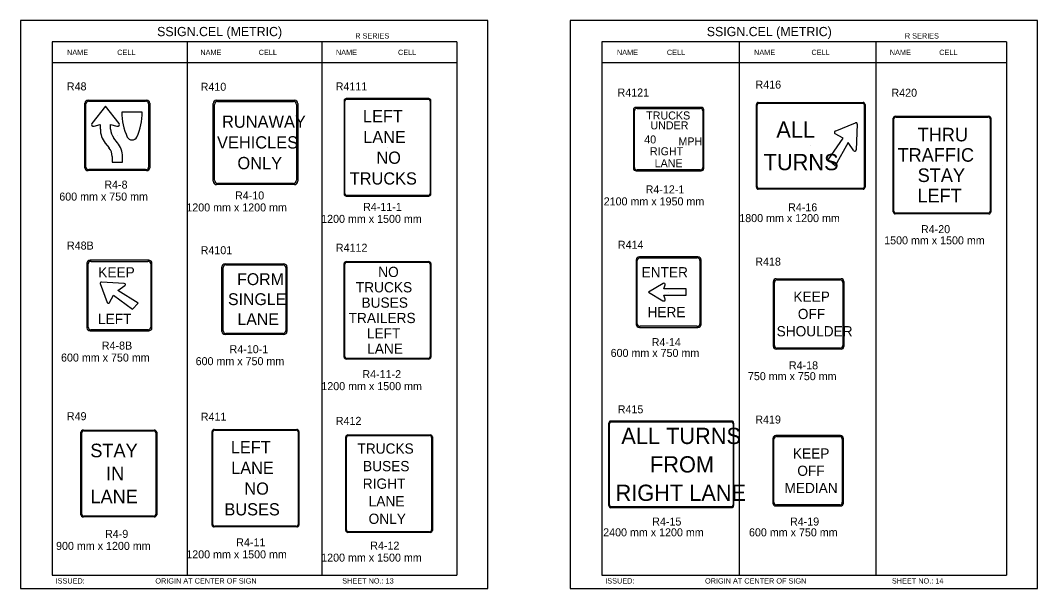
# Model space of a CAD drawing. Extents: x -12 to 6962, y -3756 to 679.
# Drawn here: x -11.9 to 369.4, y -235.4 to -22.3 of the extents above; entities that cross this region are included whole.
import ezdxf

# ---------------------------------------------------------------- set-up
doc = ezdxf.new("R2010")
doc.units = 0
for name, color, linetype in [('Level 1', 7, 'Continuous'), ('Level 2', 7, 'Continuous'), ('Level 3', 7, 'Continuous'), ('Level 63', 7, 'Continuous')]:
    doc.layers.add(name, color=color, linetype=linetype)

msp = doc.modelspace()

# ---------------------------------------------------------------- linework, layer by layer
at = {"layer": 'Level 1'}
for p, q in [((151.75, -30.35), (0, -30.35)), ((0, -30.35), (0, -230.35)), ((50.58, -30.35), (50.58, -230.35)), ((101.17, -30.35), (101.17, -230.35)), ((151.75, -30.35), (151.75, -230.35)), ((357.75, -30.35), (205.99, -30.35)), ((205.99, -30.35), (205.99, -230.35)), ((257.54, -30.35), (257.54, -230.35)), ((308.7, -30.35), (308.7, -230.35)), ((357.75, -30.35), (357.75, -230.35)), ((151.75, -38.27), (0, -38.27)), ((357.75, -38.27), (205.99, -38.27)), ((13.85, -52.65), (35.07, -52.65)), ((62.06, -52.68), (90.47, -52.68)), ((109.78, -87.26), (109.78, -52.58)), ((110.53, -51.91), (140.93, -51.91)), ((141.68, -52.58), (141.68, -87.26)), ((12.72, -77.3), (12.72, -53.63)), ((20.02, -54.53), (14.89, -60.96)), ((25.13, -60.96), (20.02, -54.53)), ((33.83, -56.72), (26.15, -56.72)), ((36.2, -53.63), (36.2, -77.3)), ((60.88, -82.26), (60.88, -53.85)), ((91.64, -53.85), (91.64, -82.26)), ((218.26, -77.51), (218.26, -56.2)), ((219.23, -55.32), (242.91, -55.32)), ((243.89, -56.2), (243.89, -77.51)), ((264.22, -84.56), (264.22, -54.16)), ((264.85, -53.41), (303.8, -53.41)), ((304.42, -54.16), (304.42, -84.56)), ((293.51, -63.87), (301.15, -60.71)), ((315.54, -93.92), (315.54, -59.24)), ((316.21, -58.56), (350.89, -58.56)), ((351.57, -59.24), (351.57, -93.92)), ((15.79, -61.99), (18.09, -61.38)), ((18.09, -61.38), (18.09, -63.12)), ((21.93, -63.12), (21.93, -61.38)), ((21.93, -61.38), (24.24, -61.99)), ((301.73, -61.24), (301.32, -70.92)), ((19.94, -68.31), (21.35, -70.07)), ((24.53, -68.19), (23.12, -66.44)), ((24.46, -65.46), (24.46, -65.46)), ((76.26, -68.06), (76.26, -68.06)), ((290.87, -74.61), (296.5, -66.44)), ((298.41, -68.17), (293.43, -76.9)), ((296.5, -66.44), (293.48, -64.86)), ((300.53, -71.24), (298.41, -68.17)), ((125.73, -69.92), (125.73, -69.92)), ((284.32, -69.36), (284.32, -69.36)), ((22.54, -73.38), (22.54, -75.46)), ((22.54, -75.46), (26.38, -75.46)), ((26.38, -75.46), (26.38, -73.38)), ((293.43, -76.9), (290.87, -74.61)), ((35.07, -78.28), (13.85, -78.28)), ((242.91, -78.39), (219.23, -78.39)), ((333.55, -76.58), (333.55, -76.58)), ((60.88, -82.26), (60.88, -82.26)), ((90.47, -83.44), (62.06, -83.44)), ((303.8, -85.31), (264.85, -85.31)), ((140.93, -87.94), (110.53, -87.94)), ((350.89, -94.59), (316.21, -94.59)), ((13.52, -137.34), (13.52, -113.66)), ((14.65, -112.69), (35.87, -112.69)), ((37, -113.66), (37, -137.34)), ((65.24, -114.04), (86.46, -114.04)), ((109.78, -148.37), (109.78, -113.69)), ((110.53, -113.01), (140.93, -113.01)), ((141.68, -113.69), (141.68, -148.37)), ((219.34, -136.05), (219.34, -112.38)), ((220.47, -111.4), (241.69, -111.4)), ((242.82, -112.38), (242.82, -136.05)), ((64.11, -138.69), (64.11, -115.02)), ((87.59, -115.02), (87.59, -138.69)), ((18.05, -121.02), (20.71, -128.12)), ((27.07, -121.02), (18.52, -120.51)), ((24.61, -123.66), (27.34, -121.73)), ((228.97, -120.95), (223.52, -124.19)), ((229.3, -123.04), (229.83, -121.52)), ((270.73, -144.24), (270.73, -120.57)), ((271.71, -119.59), (295.38, -119.59)), ((296.36, -120.57), (296.36, -144.24)), ((21.57, -128.15), (23.05, -125.38)), ((23.05, -125.38), (30.15, -130.66)), ((32.25, -128.36), (24.61, -123.66)), ((25.26, -125.5), (25.26, -125.5)), ((223.52, -124.19), (228.95, -127.45)), ((229.83, -126.88), (229.28, -125.36)), ((229.28, -125.36), (237.63, -125.36)), ((237.63, -123.04), (229.3, -123.04)), ((231.08, -124.21), (231.08, -124.21)), ((237.63, -125.36), (237.63, -123.04)), ((30.15, -130.66), (32.25, -128.36)), ((75.85, -126.85), (75.85, -126.85)), ((125.73, -131.03), (125.73, -131.03)), ((283.55, -132.41), (283.55, -132.41)), ((241.69, -137.03), (220.47, -137.03)), ((35.87, -138.32), (14.65, -138.32)), ((86.46, -139.67), (65.24, -139.67)), ((295.38, -145.22), (271.71, -145.22)), ((140.93, -149.04), (110.53, -149.04)), ((208.92, -203.99), (208.92, -173.59)), ((209.46, -172.84), (254.68, -172.84)), ((255.22, -173.59), (255.22, -203.99)), ((11.14, -207.42), (11.14, -177.02)), ((12.02, -176.26), (38.01, -176.26)), ((38.89, -177.02), (38.89, -207.42)), ((60.28, -211.32), (60.28, -176.65)), ((61.04, -175.97), (91.44, -175.97)), ((92.19, -176.65), (92.19, -211.32)), ((110.06, -213.58), (110.06, -178.47)), ((110.36, -213.36), (110.36, -178.69)), ((110.87, -177.74), (141.76, -177.74)), ((111.11, -178.01), (141.51, -178.01)), ((142.27, -178.69), (142.27, -213.36)), ((142.57, -178.47), (142.57, -213.58)), ((271.51, -178.37), (295.19, -178.37)), ((270.53, -203.03), (270.53, -179.35)), ((296.16, -179.35), (296.16, -203.03)), ((232.07, -188.79), (232.07, -188.79)), ((25.02, -192.22), (25.02, -192.22)), ((76.24, -193.99), (76.24, -193.99)), ((283.35, -191.19), (283.35, -191.19)), ((126.31, -196.03), (126.31, -196.03)), ((126.31, -196.03), (126.31, -196.03)), ((254.68, -204.74), (209.46, -204.74)), ((295.19, -204), (271.51, -204)), ((38.01, -208.17), (12.02, -208.17)), ((91.44, -212), (61.04, -212)), ((141.76, -214.31), (110.87, -214.31)), ((141.51, -214.04), (111.11, -214.04)), ((0, -230.35), (151.75, -230.35)), ((205.99, -230.35), (357.75, -230.35))]:
    msp.add_line(p, q, dxfattribs=at)
for centre, radius, start, end in [((62.06, -53.85), 1.17, 90, 180), ((90.47, -53.85), 1.17, 0, 90), ((316.21, -59.24), 0.677, 90, 180), ((350.89, -59.24), 0.677, 0, 90), ((62.06, -82.26), 1.17, 180, 270), ((90.47, -82.26), 1.17, 270, 0), ((316.21, -93.92), 0.677, 180, 270), ((350.89, -93.92), 0.677, 270, 0), ((271.71, -120.57), 0.977, 90, 180), ((271.71, -144.24), 0.977, 180, 270), ((295.38, -144.24), 0.977, 270, 0), ((271.51, -179.35), 0.977, 90, 180), ((295.19, -179.35), 0.977, 0, 90), ((271.51, -203.03), 0.977, 180, 270), ((295.19, -203.03), 0.977, 270, 0)]:
    msp.add_arc(centre, radius, start, end, dxfattribs=at)
for centre, major_axis, ratio, start_param, end_param in [((13.85, -53.63), (-1.13, 0), 0.866667, 4.712389, 6.283185), ((35.07, -53.63), (-1.13, 0), 0.866667, 3.141593, 4.712389), ((110.53, -52.58), (-0.752, 0), 0.9, 4.712389, 6.283185), ((140.93, -52.58), (-0.752, 0), 0.9, 3.141593, 4.712389), ((55.02, -56.8), (-28.87, 0), 0.866667, 6.279909, 6.663033), ((5.07, -56.82), (28.76, 0), 0.866667, 5.902613, 6.287187), ((219.23, -56.2), (-0.977, 0), 0.9, 4.712389, 6.283185), ((242.91, -56.2), (-0.977, 0), 0.9, 3.141593, 4.712389), ((264.85, -54.16), (0, -0.752), 0.83475, 3.141593, 4.712389), ((303.8, -54.16), (0, 0.752), 0.83475, 4.712389, 6.283185), ((15.57, -61.33), (-0.801, 0), 0.866667, 5.710118, 8.143254), ((24.47, -61.33), (0.801, 0), 0.866667, 4.423116, 6.856252), ((301.29, -61.22), (0, -0.534), 0.83475, 1.527577, 3.478447), ((28.72, -63.12), (10.62, 0), 0.866667, 3.14236, 3.740294), ((28.66, -63.13), (6.72, 0), 0.866667, 3.141339, 3.744924), ((293.64, -64.37), (0, -0.53), 0.83475, 3.451897, 5.881452), ((15.81, -73.38), (-10.57, 0), 0.866667, 3.141593, 3.744195), ((29.99, -65.47), (1.92, 0), 0.866667, 3.517117, 5.907661), ((15.85, -73.38), (6.69, 0), 0.866667, 6.282648, 6.891725), ((300.87, -70.9), (0, 0.529), 0.83475, 2.250511, 4.671837), ((13.85, -77.3), (1.13, 0), 0.866667, 3.141593, 4.712389), ((35.07, -77.3), (1.13, 0), 0.866667, 4.712389, 6.283185), ((219.23, -77.51), (0.977, 0), 0.9, 3.141593, 4.712389), ((242.91, -77.51), (0.977, 0), 0.9, 4.712389, 6.283185), ((110.53, -87.26), (0.752, 0), 0.9, 3.141593, 4.712389), ((140.93, -87.26), (0.752, 0), 0.9, 4.712389, 6.283185), ((264.85, -84.56), (0, -0.752), 0.83475, 4.712389, 6.283185), ((303.8, -84.56), (0, 0.752), 0.83475, 3.141593, 4.712389), ((14.65, -113.66), (-1.13, 0), 0.866667, 4.712389, 6.283185), ((35.87, -113.66), (-1.13, 0), 0.866667, 3.141593, 4.712389), ((65.24, -115.02), (-1.13, 0), 0.866667, 4.712389, 6.283185), ((86.46, -115.02), (-1.13, 0), 0.866667, 3.141593, 4.712389), ((110.53, -113.69), (-0.752, 0), 0.9, 4.712389, 6.283185), ((140.93, -113.69), (-0.752, 0), 0.9, 3.141593, 4.712389), ((220.47, -112.38), (-1.13, 0), 0.866667, 4.712389, 6.283185), ((241.69, -112.38), (-1.13, 0), 0.866667, 3.141593, 4.712389), ((18.49, -120.9), (-0.473, 0), 0.866667, 4.637334, 6.588204), ((27.06, -121.42), (0.469, 0), 0.866667, 5.375922, 7.805476), ((229.26, -121.38), (0.592, 0), 0.866667, 6.014589, 8.386103), ((21.14, -127.99), (0.469, 0), 0.866667, 3.443944, 5.86527), ((229.26, -127.02), (-0.598, 0), 0.866667, 1.019875, 3.40872), ((220.47, -136.05), (1.13, 0), 0.866667, 3.141593, 4.712389), ((241.69, -136.05), (1.13, 0), 0.866667, 4.712389, 6.283185), ((14.65, -137.34), (1.13, 0), 0.866667, 3.141593, 4.712389), ((35.87, -137.34), (1.13, 0), 0.866667, 4.712389, 6.283185), ((65.24, -138.69), (1.13, 0), 0.866667, 3.141593, 4.712389), ((86.46, -138.69), (1.13, 0), 0.866667, 4.712389, 6.283185), ((110.53, -148.37), (0.752, 0), 0.9, 3.141593, 4.712389), ((140.93, -148.37), (0.752, 0), 0.9, 4.712389, 6.283185), ((209.46, -173.59), (0, -0.752), 0.71875, 3.141593, 4.712389), ((254.68, -173.59), (0, 0.752), 0.71875, 4.712389, 6.283185), ((12.02, -177.02), (-0.877, 0), 0.857082, 4.712389, 6.283185), ((38.01, -177.02), (-0.877, 0), 0.857082, 3.141593, 4.712389), ((61.04, -176.65), (-0.752, 0), 0.9, 4.712389, 6.283185), ((91.44, -176.65), (-0.752, 0), 0.9, 3.141593, 4.712389), ((110.87, -178.47), (-0.813, 0), 0.9, 4.712389, 6.283185), ((111.11, -178.69), (-0.752, 0), 0.9, 4.712389, 6.283185), ((141.51, -178.69), (-0.752, 0), 0.9, 3.141593, 4.712389), ((141.76, -178.47), (-0.813, 0), 0.9, 3.141593, 4.712389), ((209.46, -203.99), (0, -0.752), 0.71875, 4.712389, 6.283185), ((254.68, -203.99), (0, 0.752), 0.71875, 3.141593, 4.712389), ((12.02, -207.42), (0.877, 0), 0.857082, 3.141593, 4.712389), ((38.01, -207.42), (0.877, 0), 0.857082, 4.712389, 6.283185), ((61.04, -211.32), (0.752, 0), 0.9, 3.141593, 4.712389), ((91.44, -211.32), (0.752, 0), 0.9, 4.712389, 6.283185), ((111.11, -213.36), (0.752, 0), 0.9, 3.141593, 4.712389), ((141.51, -213.36), (0.752, 0), 0.9, 4.712389, 6.283185), ((110.87, -213.58), (0.813, 0), 0.9, 3.141593, 4.712389), ((141.76, -213.58), (0.813, 0), 0.9, 4.712389, 6.283185)]:
    msp.add_ellipse(centre, major_axis=major_axis, ratio=ratio, start_param=start_param, end_param=end_param, dxfattribs=at)
at = {"layer": 'Level 3'}
for p, q in [((12.27, -77.61), (12.27, -53.31)), ((13.49, -52.26), (35.43, -52.26)), ((36.65, -53.31), (36.65, -77.61)), ((61.68, -52.21), (90.84, -52.21)), ((109.47, -52.37), (109.47, -87.48)), ((141.17, -51.64), (110.29, -51.64)), ((141.98, -87.48), (141.98, -52.37)), ((264.65, -53.1), (304, -53.1)), ((60.41, -82.64), (60.41, -53.48)), ((92.11, -53.48), (92.11, -82.64)), ((217.86, -55.92), (217.86, -77.79)), ((243.22, -54.97), (218.92, -54.97)), ((244.28, -77.79), (244.28, -55.92)), ((263.97, -84.8), (263.97, -53.92)), ((304.68, -53.92), (304.68, -84.8)), ((315.27, -94.13), (315.27, -59.02)), ((316, -58.29), (351.11, -58.29)), ((351.84, -59.02), (351.84, -94.13)), ((35.43, -78.67), (13.49, -78.67)), ((218.92, -78.74), (243.22, -78.74)), ((90.84, -83.91), (61.68, -83.91)), ((304, -85.61), (264.65, -85.61)), ((110.29, -88.21), (141.17, -88.21)), ((351.11, -94.86), (316, -94.86)), ((13.07, -113.35), (13.07, -137.65)), ((36.23, -112.29), (14.29, -112.29)), ((37.45, -137.65), (37.45, -113.35)), ((64.88, -113.65), (86.82, -113.65)), ((109.47, -148.58), (109.47, -113.47)), ((110.29, -112.74), (141.17, -112.74)), ((141.98, -113.47), (141.98, -148.58)), ((218.89, -112.06), (218.89, -136.36)), ((242.05, -111.01), (220.11, -111.01)), ((243.27, -136.36), (243.27, -112.06)), ((63.66, -139.01), (63.66, -114.7)), ((88.04, -114.7), (88.04, -139.01)), ((270.34, -144.56), (270.34, -120.26)), ((271.39, -119.2), (295.7, -119.2)), ((296.75, -120.26), (296.75, -144.56)), ((14.29, -138.71), (36.23, -138.71)), ((86.82, -140.06), (64.88, -140.06)), ((220.11, -137.42), (242.05, -137.42)), ((295.7, -145.61), (271.39, -145.61)), ((141.17, -149.32), (110.29, -149.32)), ((208.7, -204.23), (208.7, -173.35)), ((209.29, -172.53), (254.85, -172.53)), ((255.43, -173.35), (255.43, -204.23)), ((10.79, -207.66), (10.79, -176.78)), ((11.74, -175.96), (38.29, -175.96)), ((39.24, -176.78), (39.24, -207.66)), ((59.98, -211.54), (59.98, -176.43)), ((60.79, -175.7), (91.68, -175.7)), ((92.49, -176.43), (92.49, -211.54)), ((110.06, -213.58), (110.06, -178.47)), ((110.87, -177.74), (141.76, -177.74)), ((142.57, -178.47), (142.57, -213.58)), ((270.14, -179.04), (270.14, -203.34)), ((295.5, -177.98), (271.2, -177.98)), ((296.56, -203.34), (296.56, -179.04)), ((254.85, -205.04), (209.29, -205.04)), ((271.2, -204.4), (295.5, -204.4)), ((38.29, -208.47), (11.74, -208.47)), ((91.68, -212.27), (60.79, -212.27)), ((141.76, -214.31), (110.87, -214.31))]:
    msp.add_line(p, q, dxfattribs=at)
for centre, radius, start, end in [((61.68, -53.48), 1.27, 90, 180), ((90.84, -53.48), 1.27, 0, 90), ((316, -59.02), 0.731, 90, 180), ((351.11, -59.02), 0.731, 0, 90), ((61.68, -82.64), 1.27, 180, 270), ((90.84, -82.64), 1.27, 270, 0), ((316, -94.13), 0.731, 180, 270), ((351.11, -94.13), 0.731, 270, 0), ((271.39, -120.26), 1.06, 90, 180), ((295.38, -120.57), 0.977, 0, 90), ((295.7, -120.26), 1.06, 0, 90), ((271.39, -144.56), 1.06, 180, 270), ((295.7, -144.56), 1.06, 270, 0), ((271.2, -179.04), 1.06, 90, 180), ((295.5, -179.04), 1.06, 0, 90), ((271.2, -203.34), 1.06, 180, 270), ((295.5, -203.34), 1.06, 270, 0)]:
    msp.add_arc(centre, radius, start, end, dxfattribs=at)
for centre, major_axis, ratio, start_param, end_param in [((13.49, -53.31), (-1.22, 0), 0.866667, 4.712389, 6.283185), ((35.43, -53.31), (-1.22, 0), 0.866667, 3.141593, 4.712389), ((110.29, -52.37), (-0.813, 0), 0.9, 4.712389, 6.283185), ((141.17, -52.37), (-0.813, 0), 0.9, 3.141593, 4.712389), ((264.65, -53.92), (0, -0.813), 0.83475, 3.141593, 4.712389), ((304, -53.92), (0, 0.813), 0.83475, 4.712389, 6.283185), ((218.92, -55.92), (-1.06, 0), 0.9, 4.712389, 6.283185), ((243.22, -55.92), (-1.06, 0), 0.9, 3.141593, 4.712389), ((13.49, -77.61), (1.22, 0), 0.866667, 3.141593, 4.712389), ((35.43, -77.61), (1.22, 0), 0.866667, 4.712389, 6.283185), ((218.92, -77.79), (1.06, 0), 0.9, 3.141593, 4.712389), ((243.22, -77.79), (1.06, 0), 0.9, 4.712389, 6.283185), ((110.29, -87.48), (0.813, 0), 0.9, 3.141593, 4.712389), ((141.17, -87.48), (0.813, 0), 0.9, 4.712389, 6.283185), ((264.65, -84.8), (0, -0.813), 0.83475, 4.712389, 6.283185), ((304, -84.8), (0, 0.813), 0.83475, 3.141593, 4.712389), ((14.29, -113.35), (-1.22, 0), 0.866667, 4.712389, 6.283185), ((36.23, -113.35), (-1.22, 0), 0.866667, 3.141593, 4.712389), ((64.88, -114.7), (-1.22, 0), 0.866667, 4.712389, 6.283185), ((86.82, -114.7), (-1.22, 0), 0.866667, 3.141593, 4.712389), ((110.29, -113.47), (-0.813, 0), 0.9, 4.712389, 6.283185), ((141.17, -113.47), (-0.813, 0), 0.9, 3.141593, 4.712389), ((220.11, -112.06), (-1.22, 0), 0.866667, 4.712389, 6.283185), ((242.05, -112.06), (-1.22, 0), 0.866667, 3.141593, 4.712389), ((220.11, -136.36), (1.22, 0), 0.866667, 3.141593, 4.712389), ((242.05, -136.36), (1.22, 0), 0.866667, 4.712389, 6.283185), ((14.29, -137.65), (1.22, 0), 0.866667, 3.141593, 4.712389), ((36.23, -137.65), (1.22, 0), 0.866667, 4.712389, 6.283185), ((64.88, -139.01), (1.22, 0), 0.866667, 3.141593, 4.712389), ((86.82, -139.01), (1.22, 0), 0.866667, 4.712389, 6.283185), ((110.29, -148.58), (0.813, 0), 0.9, 3.141593, 4.712389), ((141.17, -148.58), (0.813, 0), 0.9, 4.712389, 6.283185), ((209.29, -173.35), (0, -0.813), 0.71875, 3.141593, 4.712389), ((254.85, -173.35), (0, 0.813), 0.71875, 4.712389, 6.283185), ((11.74, -176.78), (-0.948, 0), 0.857082, 4.712389, 6.283185), ((38.29, -176.78), (-0.948, 0), 0.857082, 3.141593, 4.712389), ((60.79, -176.43), (-0.813, 0), 0.9, 4.712389, 6.283185), ((91.68, -176.43), (-0.813, 0), 0.9, 3.141593, 4.712389), ((110.87, -178.47), (-0.813, 0), 0.9, 4.712389, 6.283185), ((141.76, -178.47), (-0.813, 0), 0.9, 3.141593, 4.712389), ((209.29, -204.23), (0, -0.813), 0.71875, 4.712389, 6.283185), ((254.85, -204.23), (0, 0.813), 0.71875, 3.141593, 4.712389), ((11.74, -207.66), (0.948, 0), 0.857082, 3.141593, 4.712389), ((38.29, -207.66), (0.948, 0), 0.857082, 4.712389, 6.283185), ((60.79, -211.54), (0.813, 0), 0.9, 3.141593, 4.712389), ((91.68, -211.54), (0.813, 0), 0.9, 4.712389, 6.283185), ((110.87, -213.58), (0.813, 0), 0.9, 3.141593, 4.712389), ((141.76, -213.58), (0.813, 0), 0.9, 4.712389, 6.283185)]:
    msp.add_ellipse(centre, major_axis=major_axis, ratio=ratio, start_param=start_param, end_param=end_param, dxfattribs=at)
at = {"layer": 'Level 63'}
for points in [[(-11.88, -235.4), (163.38, -235.4), (163.38, -22.31), (-11.88, -22.31)], [(194.12, -235.4), (369.38, -235.4), (369.38, -22.31), (194.12, -22.31)]]:
    msp.add_lwpolyline(points, close=True, dxfattribs=at)

# ---------------------------------------------------------------- texts
at = {"layer": 'Level 1'}
for s, height, p in [('LEFT', 4.572, (116.51, -60.55)), ('TRUCKS', 3, (222.67, -59.48)), ('RUNAWAY', 4.596, (63.71, -62.59)), ('UNDER', 3, (224.24, -63.18)), ('ALL', 6.096, (271.44, -66.31)), ('LANE', 4.572, (116.63, -68.32)), ('THRU', 5.08, (324.41, -67.69)), ('VEHICLES', 4.596, (61.83, -70.36)), ('40', 3, (221.94, -68.47)), ('MPH', 3, (234.75, -69.2)), ('NO', 4.572, (121.57, -76.09)), ('RIGHT', 3, (224.07, -72.9)), ('TURNS', 6.096, (266.7, -78.5)), ('TRAFFIC', 5.08, (316.87, -75.31)), ('ONLY', 4.596, (69.48, -78.12)), ('LANE', 3, (225.83, -77.39)), ('TRUCKS', 4.572, (111.59, -83.87)), ('STAY', 5.08, (324.41, -82.93)), ('LEFT', 5.08, (324.33, -90.55)), ('KEEP', 3.83, (17.33, -118.69)), ('FORM', 4.445, (69.38, -121.58)), ('NO', 3.84, (122.24, -118.55)), ('ENTER', 3.83, (220.95, -118.68)), ('TRUCKS', 3.84, (113.85, -124.31)), ('SINGLE', 4.445, (65.95, -129.08)), ('KEEP', 3.83, (277.85, -127.85)), ('BUSES', 3.84, (115.97, -130.07)), ('LEFT', 3.83, (17.24, -136.18)), ('LANE', 4.445, (69.48, -136.57)), ('TRAILERS', 3.84, (111.15, -135.83)), ('HERE', 3.83, (223.16, -133.63)), ('OFF', 3.83, (279.5, -134.32)), ('SHOULDER', 3.83, (271.56, -140.79)), ('LEFT', 3.84, (117.99, -141.59)), ('LANE', 3.84, (118.09, -147.35)), ('ALL TURNS', 6.096, (213.35, -181.17)), ('STAY', 5.08, (14.35, -186.12)), ('LEFT', 4.572, (67.02, -184.61)), ('TRUCKS', 3.84, (114.44, -184.78)), ('KEEP', 3.83, (277.66, -186.63)), ('FROM', 6.096, (224.1, -191.84)), ('IN', 5.08, (20.26, -194.76)), ('LANE', 4.572, (67.14, -192.39)), ('BUSES', 3.84, (116.55, -191.36)), ('OFF', 3.83, (279.31, -193.1)), ('RIGHT', 3.84, (116.45, -197.95)), ('NO', 4.572, (72.08, -200.16)), ('RIGHT LANE', 6.096, (211.18, -202.5)), ('MEDIAN', 3.83, (274.51, -199.57)), ('LANE', 5.08, (14.4, -203.39)), ('LANE', 3.84, (118.67, -204.53)), ('BUSES', 4.572, (64.62, -207.93)), ('ONLY', 3.84, (118.64, -211.11))]:
    msp.add_text(s, height=height, dxfattribs=at).set_placement(p)
at = {"layer": 'Level 2'}
for s, p in [('R48', (5.56, -48.58)), ('R410', (55.7, -48.71)), ('R4111', (106.31, -48.57)), ('R416', (263.64, -47.91)), ('R4121', (211.93, -50.87)), ('R420', (314.59, -50.95)), ('R48B', (5.59, -108.25)), ('R4112', (106.37, -109.07)), ('R414', (212.06, -107.96)), ('R4101', (55.7, -109.99)), ('R418', (263.56, -114.27)), ('R415', (212.01, -169.65)), ('R49', (5.56, -172.23)), ('R411', (55.75, -172.42)), ('R412', (106.35, -173.98)), ('R419', (263.56, -173.48))]:
    msp.add_text(s, height=3, dxfattribs=at).set_placement(p)
at = {"layer": 'Level 3'}
for s, height, p in [('SSIGN.CEL (METRIC)', 3.4642, (39.38, -28.24)), ('SSIGN.CEL (METRIC)', 3.4642, (245.38, -28.24)), ('R SERIES', 1.979, (113.63, -29.12)), ('R SERIES', 1.979, (319.62, -29.12)), ('NAME', 1.98, (5.62, -35.31)), ('CELL', 1.98, (24.43, -35.31)), ('NAME', 1.98, (55.58, -35.31)), ('CELL', 1.98, (77.45, -35.31)), ('NAME', 1.98, (106.4, -35.31)), ('CELL', 1.98, (129.66, -35.31)), ('NAME', 1.98, (211.7, -35.31)), ('CELL', 1.98, (230.43, -35.31)), ('NAME', 1.98, (263.1, -35.31)), ('CELL', 1.98, (284.6, -35.31)), ('NAME', 1.98, (313.97, -35.31)), ('CELL', 1.98, (332.5, -35.31)), ('R4-8', 3, (19.6, -85.39)), ('600 mm x 750 mm', 3, (2.72, -89.89)), ('R4-10', 3, (68.58, -89.46)), ('R4-12-1', 3, (222.47, -87.19)), ('1200 mm x 1200 mm', 3, (50.33, -93.96)), ('R4-11-1', 3, (116.58, -93.74)), ('2100 mm x 1950 mm', 3, (206.75, -91.69)), ('R4-16', 3, (275.85, -93.91)), ('1200 mm x 1500 mm', 3, (100.86, -98.24)), ('1800 mm x 1200 mm', 3, (257.55, -97.96)), ('R4-20', 3, (325.65, -102.1)), ('1500 mm x 1500 mm', 3, (311.86, -106.3)), ('R4-8B', 3, (18.66, -145.75)), ('R4-10-1', 3, (66.53, -147.11)), ('R4-14', 3, (224.73, -144.46)), ('600 mm x 750 mm', 3, (3.37, -150.25)), ('600 mm x 750 mm', 3, (53.81, -151.61)), ('600 mm x 750 mm', 3, (209.35, -148.51)), ('R4-18', 3, (276.16, -153.17)), ('R4-11-2', 3, (116.31, -156.47)), ('750 mm x 750 mm', 3, (260.79, -157.22)), ('1200 mm x 1500 mm', 3, (100.93, -160.97)), ('R4-15', 3, (224.93, -211.73)), ('R4-19', 3, (276.56, -211.73)), ('R4-9', 3, (19.86, -216.36)), ('2400 mm x 1200 mm', 3, (206.55, -215.78)), ('600 mm x 750 mm', 3, (261.2, -215.78)), ('R4-11', 3, (69.03, -219.54)), ('900 mm x 1200 mm', 3, (1.5, -220.86)), ('1200 mm x 1500 mm', 3, (50.31, -224.04)), ('R4-12', 3, (119.25, -220.76)), ('1200 mm x 1500 mm', 3, (100.87, -225.26)), ('ISSUED:', 1.98, (1.34, -233.48)), ('ORIGIN AT CENTER OF SIGN', 1.9795, (38.72, -233.48)), ('SHEET NO.: 13', 1.9795, (108.76, -233.48)), ('ISSUED:', 1.98, (207.33, -233.48)), ('ORIGIN AT CENTER OF SIGN', 1.9795, (244.72, -233.48)), ('SHEET NO.: 14', 1.9795, (314.76, -233.48))]:
    msp.add_text(s, height=height, dxfattribs=at).set_placement(p)

doc.saveas('drawing.dxf')
